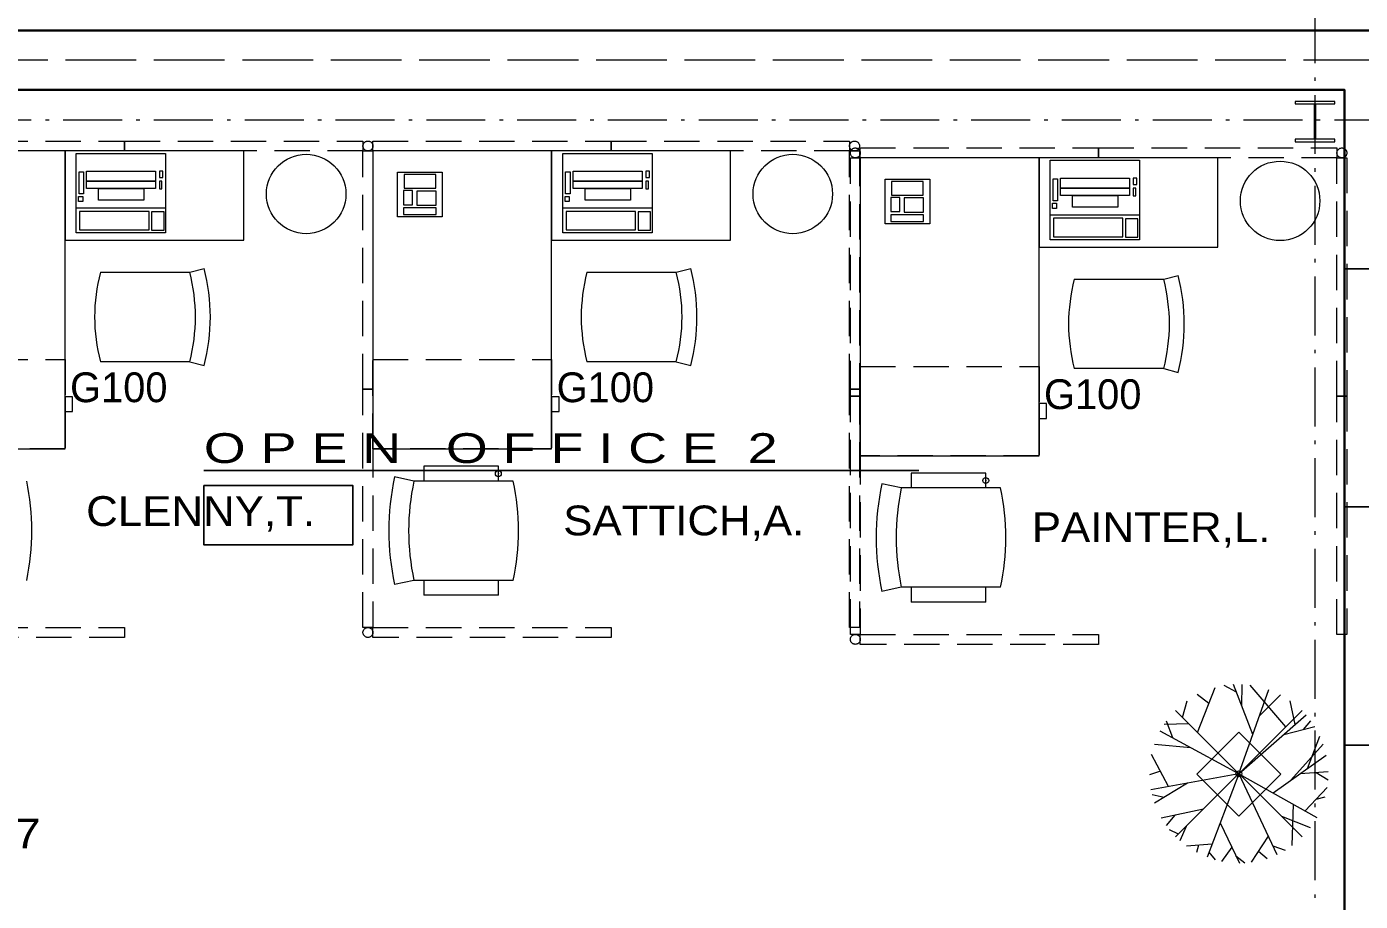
# Model space of a CAD drawing. Extents: x -118748 to -117136, y -118748 to -117596.
# Drawn here: x -117681.9 to -117467, y -118094.8 to -117953.8 of the extents above; entities that cross this region are included whole.
import ezdxf
from ezdxf.enums import TextEntityAlignment as Align

# ---------------------------------------------------------------- set-up
doc = ezdxf.new("R2010")
doc.units = 0
doc.header["$LTSCALE"] = 1.9
doc.header["$PDMODE"] = 32
doc.header["$PDSIZE"] = 0.95
for name, pattern in [('DOT_DASHED', [7.7, 5, -1.2, 0.3, -1.2]), ('LONG_DASHED', [7.5, 6, -1.5]), ('MEDIUM_DASHED', [4.5, 3, -1.5])]:
    doc.linetypes.add(name, pattern=pattern)
for name, color, linetype, lineweight in [('10', 7, 'DOT_DASHED', 13), ('12', 7, 'Continuous', 13), ('15', 7, 'Continuous', 13), ('16', 7, 'Continuous', 13), ('17', 7, 'Continuous', 25), ('20', 7, 'MEDIUM_DASHED', 13), ('23', 7, 'Continuous', 25), ('3', 7, 'Continuous', 35), ('30', 7, 'Continuous', 13), ('4', 7, 'Continuous', 35), ('45', 7, 'Continuous', 25), ('5', 7, 'Continuous', 13), ('6', 7, 'Continuous', 13), ('60', 7, 'LONG_DASHED', 13), ('9', 7, 'Continuous', 35)]:
    doc.layers.add(name, color=color, linetype=linetype, lineweight=lineweight)
doc.layers.add('53', color=7, linetype='Continuous')

msp = doc.modelspace()

# ---------------------------------------------------------------- linework, layer by layer
at = {"layer": '10'}
for p, q in [((-117474.321, -117628.339), (-117474.321, -118698.41)), ((-118641.571, -117968.81), (-117285.521, -117968.81))]:
    msp.add_line(p, q, dxfattribs=at)
at = {"layer": '12'}
msp.add_lwpolyline([(-117477.504, -117972.362), (-117471.088, -117972.362), (-117471.088, -117971.966), (-117474.172, -117971.966), (-117474.172, -117966.262), (-117471.088, -117966.262), (-117471.088, -117965.866), (-117477.504, -117965.866), (-117477.504, -117966.262), (-117474.42, -117966.262), (-117474.42, -117971.966), (-117477.504, -117971.966)], close=True, dxfattribs=at)
at = {"layer": '15', "lineweight": 25}
for p, q in [((-117459.921, -117954.41), (-117829.521, -117954.41)), ((-117469.521, -117964.01), (-117829.521, -117964.01)), ((-117469.521, -117992.81), (-117469.521, -117964.01)), ((-117469.521, -117992.81), (-117459.921, -117992.81)), ((-117469.521, -118031.21), (-117459.921, -118031.21)), ((-117469.521, -118069.61), (-117469.521, -118031.21)), ((-117469.521, -118069.61), (-117459.921, -118069.61))]:
    msp.add_line(p, q, dxfattribs=at)
at = {"layer": '15'}
for p, q in [((-117669.998, -117993.398), (-117655.598, -117993.398)), ((-117655.598, -117993.398), (-117653.276, -117992.791)), ((-117591.598, -117993.398), (-117577.198, -117993.398)), ((-117577.198, -117993.398), (-117574.876, -117992.791)), ((-117513.069, -117994.511), (-117498.669, -117994.511)), ((-117498.669, -117994.511), (-117496.347, -117993.905)), ((-117655.598, -118007.798), (-117669.998, -118007.798)), ((-117655.598, -118007.798), (-117653.276, -118008.404)), ((-117577.198, -118007.798), (-117591.598, -118007.798)), ((-117577.198, -118007.798), (-117574.876, -118008.404)), ((-117498.669, -118008.911), (-117513.069, -118008.911)), ((-117498.669, -118008.911), (-117496.347, -118009.518)), ((-117605.871, -118024.64), (-117617.871, -118024.64)), ((-117617.871, -118024.64), (-117617.871, -118027.04)), ((-117605.871, -118027.04), (-117605.871, -118024.64)), ((-117527.342, -118025.754), (-117539.342, -118025.754)), ((-117539.342, -118025.754), (-117539.342, -118028.154)), ((-117527.342, -118028.154), (-117527.342, -118025.754)), ((-117619.471, -118027.04), (-117622.599, -118026.364)), ((-117603.471, -118027.04), (-117619.471, -118027.04)), ((-117605.871, -118027.04), (-117617.871, -118027.04)), ((-117540.942, -118028.154), (-117544.07, -118027.478)), ((-117524.942, -118028.154), (-117540.942, -118028.154)), ((-117527.342, -118028.154), (-117539.342, -118028.154)), ((-117619.471, -118043.04), (-117622.599, -118043.716)), ((-117603.471, -118043.04), (-117619.471, -118043.04)), ((-117605.871, -118043.04), (-117617.871, -118043.04)), ((-117617.871, -118043.04), (-117617.871, -118045.44)), ((-117605.871, -118045.44), (-117605.871, -118043.04)), ((-117540.942, -118044.154), (-117544.07, -118044.83)), ((-117524.942, -118044.154), (-117540.942, -118044.154)), ((-117527.342, -118044.154), (-117539.342, -118044.154)), ((-117539.342, -118044.154), (-117539.342, -118046.554)), ((-117527.342, -118046.554), (-117527.342, -118044.154)), ((-117605.871, -118045.44), (-117617.871, -118045.44)), ((-117527.342, -118046.554), (-117539.342, -118046.554))]:
    msp.add_line(p, q, dxfattribs=at)
for points in [[(-117704.485, -118021.839), (-117675.685, -118021.839), (-117675.685, -117973.839), (-117704.485, -117973.839)], [(-117675.685, -117988.239), (-117646.885, -117988.239), (-117646.885, -117973.839), (-117675.685, -117973.839)], [(-117626.085, -118021.839), (-117597.285, -118021.839), (-117597.285, -117973.839), (-117626.085, -117973.839)], [(-117597.285, -117988.239), (-117568.485, -117988.239), (-117568.485, -117973.839), (-117597.285, -117973.839)], [(-117547.556, -118022.953), (-117518.756, -118022.953), (-117518.756, -117974.953), (-117547.556, -117974.953)], [(-117518.756, -117989.353), (-117489.956, -117989.353), (-117489.956, -117974.953), (-117518.756, -117974.953)]]:
    msp.add_lwpolyline(points, close=True, dxfattribs=at)
for centre, radius, start, end in [((-117642.448, -118000.597), 28.475, 165.35367, 194.64632), ((-117683.148, -118000.597), 28.475, 345.35367, 14.64632), ((-117683.148, -118000.597), 30.875, 345.35367, 14.64632), ((-117564.048, -118000.597), 28.475, 165.35367, 194.64632), ((-117604.748, -118000.597), 28.475, 345.35367, 14.64632), ((-117604.748, -118000.597), 30.875, 345.35367, 14.64632), ((-117485.519, -118001.711), 28.475, 165.35367, 194.64632), ((-117526.219, -118001.711), 28.475, 345.35367, 14.64632), ((-117526.219, -118001.711), 30.875, 345.35367, 14.64632), ((-117718.879, -118035.04), 37.863, 347.80217, 12.19783), ((-117582.463, -118035.04), 41.063, 167.80217, 192.19782), ((-117582.463, -118035.04), 37.863, 167.80217, 192.19782), ((-117582.463, -118035.04), 37.863, 167.80217, 192.19782), ((-117640.479, -118035.04), 37.863, 347.80217, 12.19783), ((-117503.934, -118036.154), 41.063, 167.80217, 192.19782), ((-117503.934, -118036.154), 37.863, 167.80217, 192.19782), ((-117503.934, -118036.154), 37.863, 167.80217, 192.19782), ((-117561.951, -118036.154), 37.863, 347.80217, 12.19783)]:
    msp.add_arc(centre, radius, start, end, dxfattribs=at)
for p in [(-117605.871, -118025.84), (-117527.342, -118026.954)]:
    msp.add_point(p, dxfattribs=at)
at = {"layer": '16'}
for p, q in [((-117673.887, -117983.025), (-117659.487, -117983.025)), ((-117595.487, -117983.025), (-117581.087, -117983.025)), ((-117516.959, -117984.139), (-117502.559, -117984.139)), ((-117469.521, -118031.21), (-117469.521, -117992.81)), ((-117469.521, -118108.01), (-117469.521, -118069.61))]:
    msp.add_line(p, q, dxfattribs=at)
for points in [[(-117673.887, -117987.025), (-117673.887, -117974.225), (-117659.487, -117974.225), (-117659.487, -117987.025)], [(-117595.487, -117987.025), (-117595.487, -117974.225), (-117581.087, -117974.225), (-117581.087, -117987.025)], [(-117516.959, -117988.139), (-117516.959, -117975.339), (-117502.559, -117975.339), (-117502.559, -117988.139)], [(-117673.43, -117980.742), (-117673.43, -117977.206), (-117672.722, -117977.206), (-117672.722, -117980.742)], [(-117672.223, -117978.704), (-117672.223, -117977.104), (-117661.114, -117977.104), (-117661.114, -117978.704)], [(-117672.223, -117979.91), (-117672.223, -117978.704), (-117661.114, -117978.704), (-117661.114, -117979.91)], [(-117660.49, -117977.123), (-117660.49, -117978.121), (-117659.907, -117978.121), (-117659.907, -117977.123)], [(-117660.49, -117978.704), (-117660.49, -117979.952), (-117660.074, -117979.952), (-117660.074, -117978.704)], [(-117614.9, -117984.461), (-117622.1, -117984.461), (-117622.1, -117977.261), (-117614.9, -117977.261)], [(-117621.065, -117979.842), (-117615.948, -117979.842), (-117615.948, -117977.637), (-117621.065, -117977.637)], [(-117595.03, -117980.742), (-117595.03, -117977.206), (-117594.322, -117977.206), (-117594.322, -117980.742)], [(-117593.823, -117978.704), (-117593.823, -117977.104), (-117582.714, -117977.104), (-117582.714, -117978.704)], [(-117593.823, -117979.91), (-117593.823, -117978.704), (-117582.714, -117978.704), (-117582.714, -117979.91)], [(-117582.09, -117977.123), (-117582.09, -117978.121), (-117581.507, -117978.121), (-117581.507, -117977.123)], [(-117582.09, -117978.704), (-117582.09, -117979.952), (-117581.674, -117979.952), (-117581.674, -117978.704)], [(-117536.371, -117985.575), (-117543.571, -117985.575), (-117543.571, -117978.375), (-117536.371, -117978.375)], [(-117542.537, -117980.956), (-117537.419, -117980.956), (-117537.419, -117978.75), (-117542.537, -117978.75)], [(-117516.501, -117981.856), (-117516.501, -117978.32), (-117515.794, -117978.32), (-117515.794, -117981.856)], [(-117515.294, -117979.818), (-117515.294, -117978.217), (-117504.185, -117978.217), (-117504.185, -117979.818)], [(-117503.561, -117978.236), (-117503.561, -117979.235), (-117502.979, -117979.235), (-117502.979, -117978.236)], [(-117670.309, -117981.783), (-117670.309, -117979.91), (-117662.986, -117979.91), (-117662.986, -117981.783)], [(-117621.149, -117982.505), (-117619.692, -117982.505), (-117619.692, -117980.216), (-117621.149, -117980.216)], [(-117619.027, -117982.588), (-117615.906, -117982.588), (-117615.906, -117980.299), (-117619.027, -117980.299)], [(-117591.909, -117981.783), (-117591.909, -117979.91), (-117584.586, -117979.91), (-117584.586, -117981.783)], [(-117515.294, -117981.024), (-117515.294, -117979.818), (-117504.185, -117979.818), (-117504.185, -117981.024)], [(-117503.561, -117979.818), (-117503.561, -117981.066), (-117503.145, -117981.066), (-117503.145, -117979.818)], [(-117673.513, -117981.99), (-117673.513, -117981.158), (-117672.847, -117981.158), (-117672.847, -117981.99)], [(-117615.906, -117983.004), (-117621.149, -117983.004), (-117621.149, -117984.086), (-117615.906, -117984.086)], [(-117595.113, -117981.99), (-117595.113, -117981.158), (-117594.447, -117981.158), (-117594.447, -117981.99)], [(-117542.62, -117983.618), (-117541.164, -117983.618), (-117541.164, -117981.33), (-117542.62, -117981.33)], [(-117540.498, -117983.702), (-117537.377, -117983.702), (-117537.377, -117981.413), (-117540.498, -117981.413)], [(-117516.584, -117983.104), (-117516.584, -117982.272), (-117515.918, -117982.272), (-117515.918, -117983.104)], [(-117513.38, -117982.896), (-117513.38, -117981.024), (-117506.058, -117981.024), (-117506.058, -117982.896)], [(-117673.346, -117983.572), (-117673.346, -117986.567), (-117662.154, -117986.567), (-117662.154, -117983.572)], [(-117661.738, -117983.655), (-117661.738, -117986.609), (-117659.741, -117986.609), (-117659.741, -117983.655)], [(-117594.946, -117983.572), (-117594.946, -117986.567), (-117583.754, -117986.567), (-117583.754, -117983.572)], [(-117583.338, -117983.655), (-117583.338, -117986.609), (-117581.341, -117986.609), (-117581.341, -117983.655)], [(-117537.377, -117984.118), (-117542.62, -117984.118), (-117542.62, -117985.2), (-117537.377, -117985.2)], [(-117516.418, -117984.686), (-117516.418, -117987.681), (-117505.226, -117987.681), (-117505.226, -117984.686)], [(-117504.809, -117984.769), (-117504.809, -117987.723), (-117502.812, -117987.723), (-117502.812, -117984.769)]]:
    msp.add_lwpolyline(points, close=True, dxfattribs=at)
at = {"layer": '17'}
msp.add_line((-117653.324, -118025.327), (-117538.124, -118025.327), dxfattribs=at)
at = {"layer": '20'}
for points in [[(-117704.485, -117973.839), (-117704.485, -117972.239), (-117666.085, -117972.239), (-117666.085, -117973.839)], [(-117666.085, -117973.839), (-117666.085, -117972.239), (-117627.685, -117972.239), (-117627.685, -117973.839)], [(-117626.085, -117973.839), (-117626.085, -117972.239), (-117587.685, -117972.239), (-117587.685, -117973.839)], [(-117587.685, -117973.839), (-117587.685, -117972.239), (-117549.285, -117972.239), (-117549.285, -117973.839)], [(-117627.685, -117973.839), (-117626.085, -117973.839), (-117626.085, -118012.239), (-117627.685, -118012.239)], [(-117627.685, -117973.839), (-117626.085, -117973.839), (-117626.085, -118012.239), (-117627.685, -118012.239)], [(-117549.285, -117973.839), (-117547.685, -117973.839), (-117547.685, -118012.239), (-117549.285, -118012.239)], [(-117547.556, -117974.953), (-117547.556, -117973.353), (-117509.156, -117973.353), (-117509.156, -117974.953)], [(-117509.156, -117974.953), (-117509.156, -117973.353), (-117470.756, -117973.353), (-117470.756, -117974.953)], [(-117549.156, -117974.953), (-117547.556, -117974.953), (-117547.556, -118013.353), (-117549.156, -118013.353)], [(-117470.756, -117974.953), (-117469.156, -117974.953), (-117469.156, -118013.353), (-117470.756, -118013.353)], [(-117627.685, -118012.239), (-117626.085, -118012.239), (-117626.085, -118050.639), (-117627.685, -118050.639)], [(-117627.685, -118012.239), (-117626.085, -118012.239), (-117626.085, -118050.639), (-117627.685, -118050.639)], [(-117549.285, -118012.239), (-117547.685, -118012.239), (-117547.685, -118050.639), (-117549.285, -118050.639)], [(-117549.156, -118013.353), (-117547.556, -118013.353), (-117547.556, -118051.753), (-117549.156, -118051.753)], [(-117470.756, -118013.353), (-117469.156, -118013.353), (-117469.156, -118051.753), (-117470.756, -118051.753)], [(-117704.485, -118052.239), (-117704.485, -118050.639), (-117666.085, -118050.639), (-117666.085, -118052.239)], [(-117626.085, -118052.239), (-117626.085, -118050.639), (-117587.685, -118050.639), (-117587.685, -118052.239)], [(-117547.556, -118053.353), (-117547.556, -118051.753), (-117509.156, -118051.753), (-117509.156, -118053.353)]]:
    msp.add_lwpolyline(points, close=True, dxfattribs=at)
for centre in [(-117626.885, -117973.039), (-117626.885, -117973.039), (-117548.485, -117973.039), (-117548.356, -117974.153), (-117469.956, -117974.153), (-117626.885, -118051.439), (-117548.356, -118052.553)]:
    msp.add_circle(centre, 0.8, dxfattribs=at)
at = {"layer": '23', "linetype": 'MEDIUM_DASHED', "lineweight": 13}
for points in [[(-117675.685, -118021.839), (-117704.485, -118021.839), (-117704.485, -118007.439), (-117675.685, -118007.439)], [(-117597.285, -118021.839), (-117626.085, -118021.839), (-117626.085, -118007.439), (-117597.285, -118007.439)], [(-117518.756, -118022.953), (-117547.556, -118022.953), (-117547.556, -118008.553), (-117518.756, -118008.553)], [(-117675.685, -118015.839), (-117674.485, -118015.839), (-117674.485, -118013.439), (-117675.685, -118013.439)], [(-117597.285, -118015.839), (-117596.085, -118015.839), (-117596.085, -118013.439), (-117597.285, -118013.439)], [(-117518.756, -118016.953), (-117517.556, -118016.953), (-117517.556, -118014.553), (-117518.756, -118014.553)]]:
    msp.add_lwpolyline(points, close=True, dxfattribs=at)
at = {"layer": '3'}
msp.add_lwpolyline([(-118098.321, -117954.41), (-117829.521, -117954.41), (-117459.921, -117954.41), (-117459.921, -118170.41), (-117370.321, -118170.41), (-117370.321, -118352.81), (-117459.921, -118352.81), (-117459.921, -118645.61), (-117704.721, -118645.61), (-117704.721, -118592.81), (-117847.121, -118592.81), (-117850.321, -118592.801), (-117860.744, -118590.984), (-117862.249, -118590.443), (-117871.571, -118585.668), (-117872.847, -118584.703), (-117880.323, -118577.368), (-117881.254, -118576.067), (-117886.205, -118566.837), (-117886.706, -118565.318), (-117888.682, -118555.032), (-117888.707, -118553.433), (-117890.316, -118553.433)], dxfattribs=at)
at = {"layer": '30'}
for p, q in [((-117493.225, -118067.537), (-117490.39, -118060.324)), ((-117486.933, -118061.071), (-117488.937, -118060.003)), ((-117484.308, -118067.882), (-117487.411, -118059.83)), ((-117486.093, -118063.252), (-117486.002, -118059.816)), ((-117478.976, -118066.624), (-117484.714, -118059.923)), ((-117495.634, -118065.128), (-117494.868, -118062.446)), ((-117491.39, -118062.869), (-117493.259, -118061.46)), ((-117486.557, -118074.205), (-117481.733, -118060.637)), ((-117483.24, -118064.878), (-117479.831, -118061.472)), ((-117477.49, -118066.282), (-117478.265, -118062.432)), ((-117496.739, -118084.387), (-117476.375, -118064.023)), ((-117476.375, -118084.387), (-117496.739, -118064.023)), ((-117494.62, -118066.142), (-117498.586, -118066.289)), ((-117497.201, -118068.422), (-117498.206, -118065.74)), ((-117486.557, -118074.205), (-117475.713, -118064.73)), ((-117479.322, -118067.883), (-117474.32, -118066.615)), ((-117476.138, -118067.076), (-117474.966, -118065.66)), ((-117486.557, -118074.205), (-117499.21, -118067.331)), ((-117475.486, -118073.354), (-117473.489, -118068.156)), ((-117497.882, -118076.28), (-117500.613, -118071.079)), ((-117494.283, -118070.008), (-117500.155, -118069.467)), ((-117478.181, -118075.262), (-117472.963, -118069.454)), ((-117481.05, -118077.294), (-117472.47, -118071.218)), ((-117499.19, -118073.788), (-117500.956, -118074.38)), ((-117486.557, -118074.205), (-117500.721, -118076.801)), ((-117486.557, -118074.205), (-117491.671, -118087.666)), ((-117486.557, -118074.205), (-117473.998, -118081.25)), ((-117486.557, -118074.205), (-117480.431, -118087.237)), ((-117476.67, -118074.192), (-117472.161, -118073.867)), ((-117474.123, -118074.008), (-117472.191, -118075.197)), ((-117494.848, -118075.724), (-117500.15, -118078.959)), ((-117475.86, -118080.206), (-117472.327, -118076.414)), ((-117498.609, -118078.019), (-117500.549, -118077.609)), ((-117477.823, -118079.104), (-117478.003, -118085.789)), ((-117474.09, -118078.305), (-117472.64, -118077.904)), ((-117492.262, -118079.91), (-117499.061, -118081.347)), ((-117496.877, -118080.885), (-117498.292, -118082.551)), ((-117479.711, -118081.051), (-117475.058, -118082.873)), ((-117496.268, -118083.916), (-117497.754, -118083.26)), ((-117495.051, -118082.699), (-117496.055, -118085.028)), ((-117489.57, -118082.136), (-117486.456, -118088.605)), ((-117490.859, -118085.527), (-117494.998, -118085.872)), ((-117493.071, -118085.711), (-117493.363, -118086.895)), ((-117487.684, -118086.054), (-117489.361, -118088.329)), ((-117481.832, -118084.258), (-117484.578, -118088.468)), ((-117481.099, -118085.816), (-117479.118, -118086.535)), ((-117491.369, -118086.869), (-117490.354, -118088.095)), ((-117487.021, -118087.431), (-117485.619, -118088.574)), ((-117483.417, -118086.688), (-117482.003, -118087.866))]:
    msp.add_line(p, q, dxfattribs=at)
msp.add_lwpolyline([(-117486.56, -118081.058), (-117479.772, -118074.27), (-117486.56, -118067.481), (-117493.348, -118074.27)], close=True, dxfattribs=at)
for centre in [(-117636.835, -117980.776), (-117558.435, -117980.776), (-117479.906, -117981.89)]:
    msp.add_circle(centre, 6.4, dxfattribs=at)
msp.add_point((-117486.557, -118074.205), dxfattribs=at)
at = {"layer": '4'}
msp.add_lwpolyline([(-118496.721, -117964.01), (-118496.721, -118636.01), (-118271.121, -118636.01), (-118271.121, -118588.01), (-118115.969, -118588.01), (-118106.1, -118586.234), (-118096.66, -118581.314), (-118089.115, -118573.804), (-118084.156, -118564.399), (-118081.154, -118548.633), (-118079.134, -118548.633), (-117884.057, -118548.587), (-117881.646, -118565.336), (-117876.897, -118574.111), (-117869.271, -118581.538), (-117859.789, -118586.351), (-117850.271, -118588.01), (-117695.121, -118588.01), (-117695.121, -118636.01), (-117469.521, -118636.01), (-117469.521, -117964.01)], close=True, dxfattribs=at)
at = {"layer": '45'}
msp.add_lwpolyline([(-117653.324, -118027.727), (-117653.324, -118037.327), (-117629.324, -118037.327), (-117629.324, -118027.727)], close=True, dxfattribs=at)
at = {"layer": '5'}
for points in [[(-117981.521, -118118.36), (-117981.521, -117964.01), (-117469.521, -117964.01), (-117469.521, -117992.81), (-117469.521, -118180.01), (-117469.521, -118292.01), (-117839.871, -118292.01), (-117839.871, -118184.81)], [(-117979.078, -117964.01), (-117469.521, -117964.01), (-117469.521, -118636.01), (-117695.121, -118636.01), (-117695.121, -118588.01), (-117850.271, -118588.01)]]:
    msp.add_lwpolyline(points, dxfattribs=at)
at = {"layer": '6'}
msp.add_lwpolyline([(-117981.521, -117964.01), (-117469.521, -117964.01), (-117469.521, -118292.01), (-117839.871, -118292.01), (-117839.871, -118184.81)], dxfattribs=at)
at = {"layer": '60'}
msp.add_lwpolyline([(-117464.721, -118175.21), (-117464.721, -117959.21), (-118501.521, -117959.21)], dxfattribs=at)

# ---------------------------------------------------------------- texts
at = {"layer": '17', "width": 1.35}
msp.add_text('O P E N   O F F I C E  2', height=4.8, dxfattribs=at).set_placement((-117653.324, -118024.127))
at = {"layer": '45', "width": 1.2}
msp.add_text('1565.482547', height=4.8, dxfattribs=at).set_placement((-117702.092, -118086.248), align=Align.CENTER)
at = {"layer": '53', "width": 1.1}
for s, p in [('CLENNY,T.', (-117672.282, -118034.277)), ('SATTICH,A.', (-117595.414, -118035.785)), ('PAINTER,L.', (-117519.916, -118036.882))]:
    msp.add_text(s, height=4.8, dxfattribs=at).set_placement(p)
at = {"layer": '9'}
for p in [(-117667.032, -118014.325), (-117588.632, -118014.325), (-117510.104, -118015.439)]:
    msp.add_text('G100', height=4.8, dxfattribs=at).set_placement(p, align=Align.CENTER)

doc.saveas('drawing.dxf')
